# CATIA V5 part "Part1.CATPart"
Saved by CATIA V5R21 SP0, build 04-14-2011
Part number: Part1
Bounding box of the stored display mesh (mm): x -100 to 100, y -54.891 to 54.891, z 0 to 20
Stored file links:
  D:\CATIA V5R21 E-RESOURCES\CATIA-V5R21\catia-v5r21-prt\c16-catia-v5r20-prt\Roll Curve Joint-(Fig16-43)\CAT_V5R21_Part1.CATPart
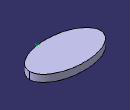
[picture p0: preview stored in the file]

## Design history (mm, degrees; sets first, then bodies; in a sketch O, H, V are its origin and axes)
Body1 (main body)
  Sketch1 on xy-plane, origin (0, 0, 0), H (1, 0, 0), V (0, 1, 0)
    point P1 (0, 0)
    ellipse A1 centre (0, 0) semi-axes 100, 55 rotation 0
    "Radius" A1 = 100
    "Radius" A1 = 55
    angle V A1 = 90
    coincidence: P1 H, P1 V
  Pad1: profile Sketch1, direction (0, 0, 1), length 20
  Point1: type OnCurve, Support edge [face of Pad1 from Sketch1.A1 | end face of Pad1], RefPoint {extremum Reference edge [face of Pad1 from Sketch1.A1 | end face of Pad1], Direction (1, 2, 3)}, Length 344.171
